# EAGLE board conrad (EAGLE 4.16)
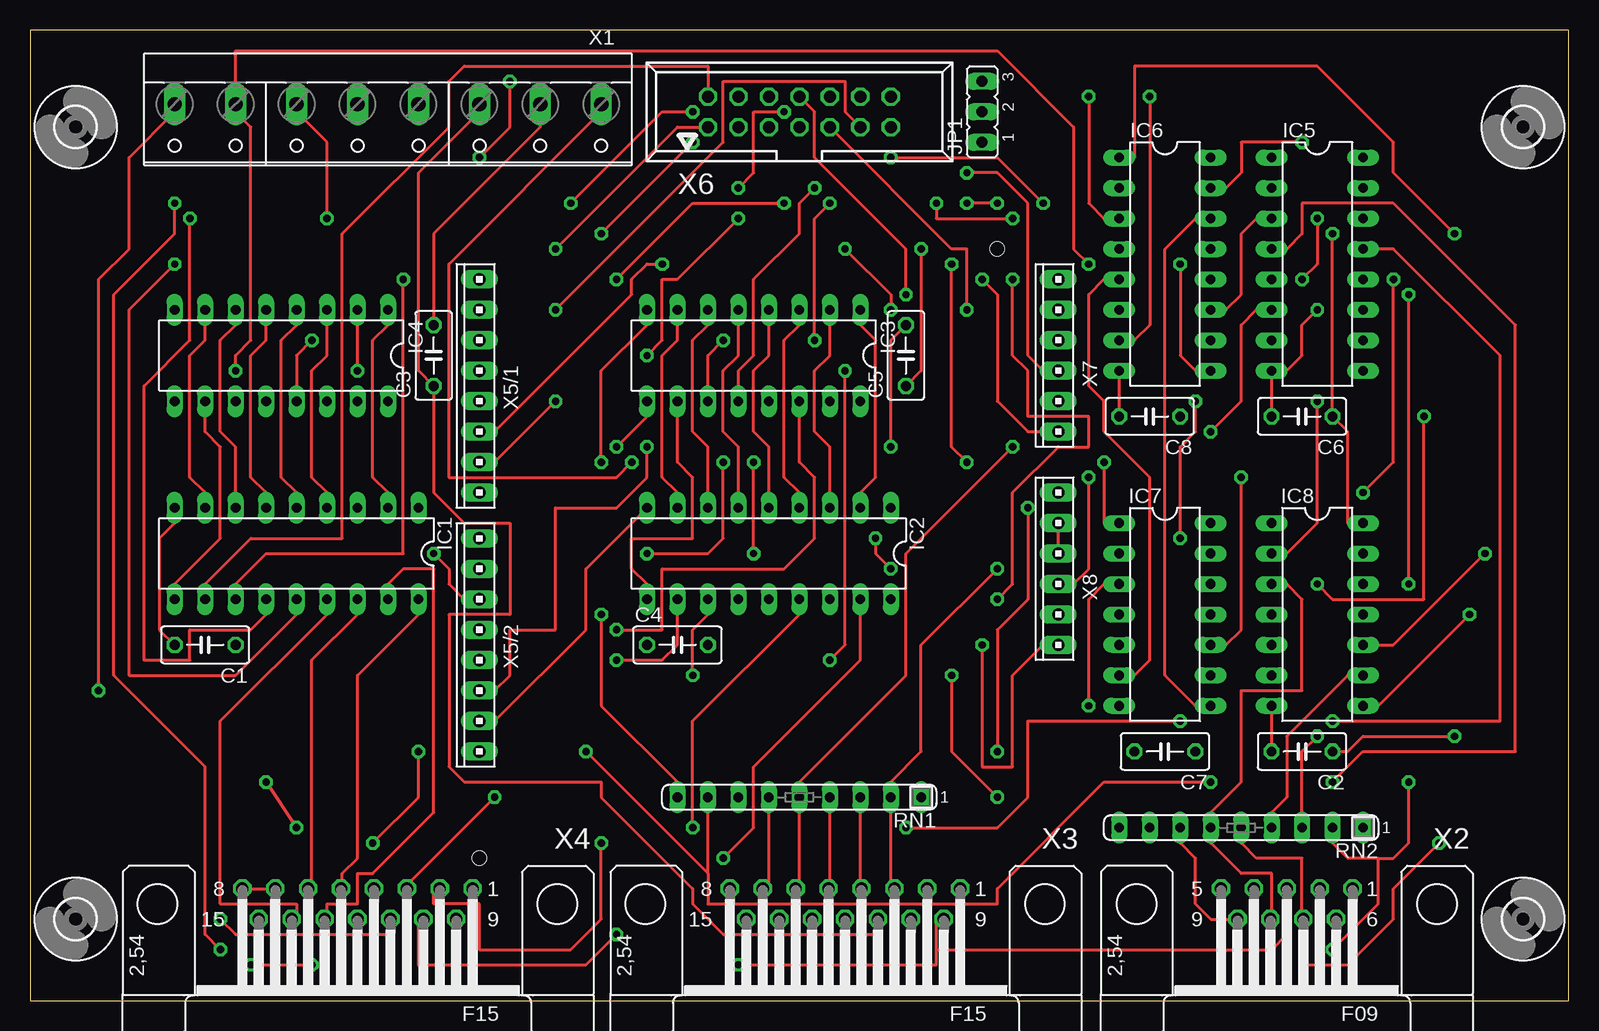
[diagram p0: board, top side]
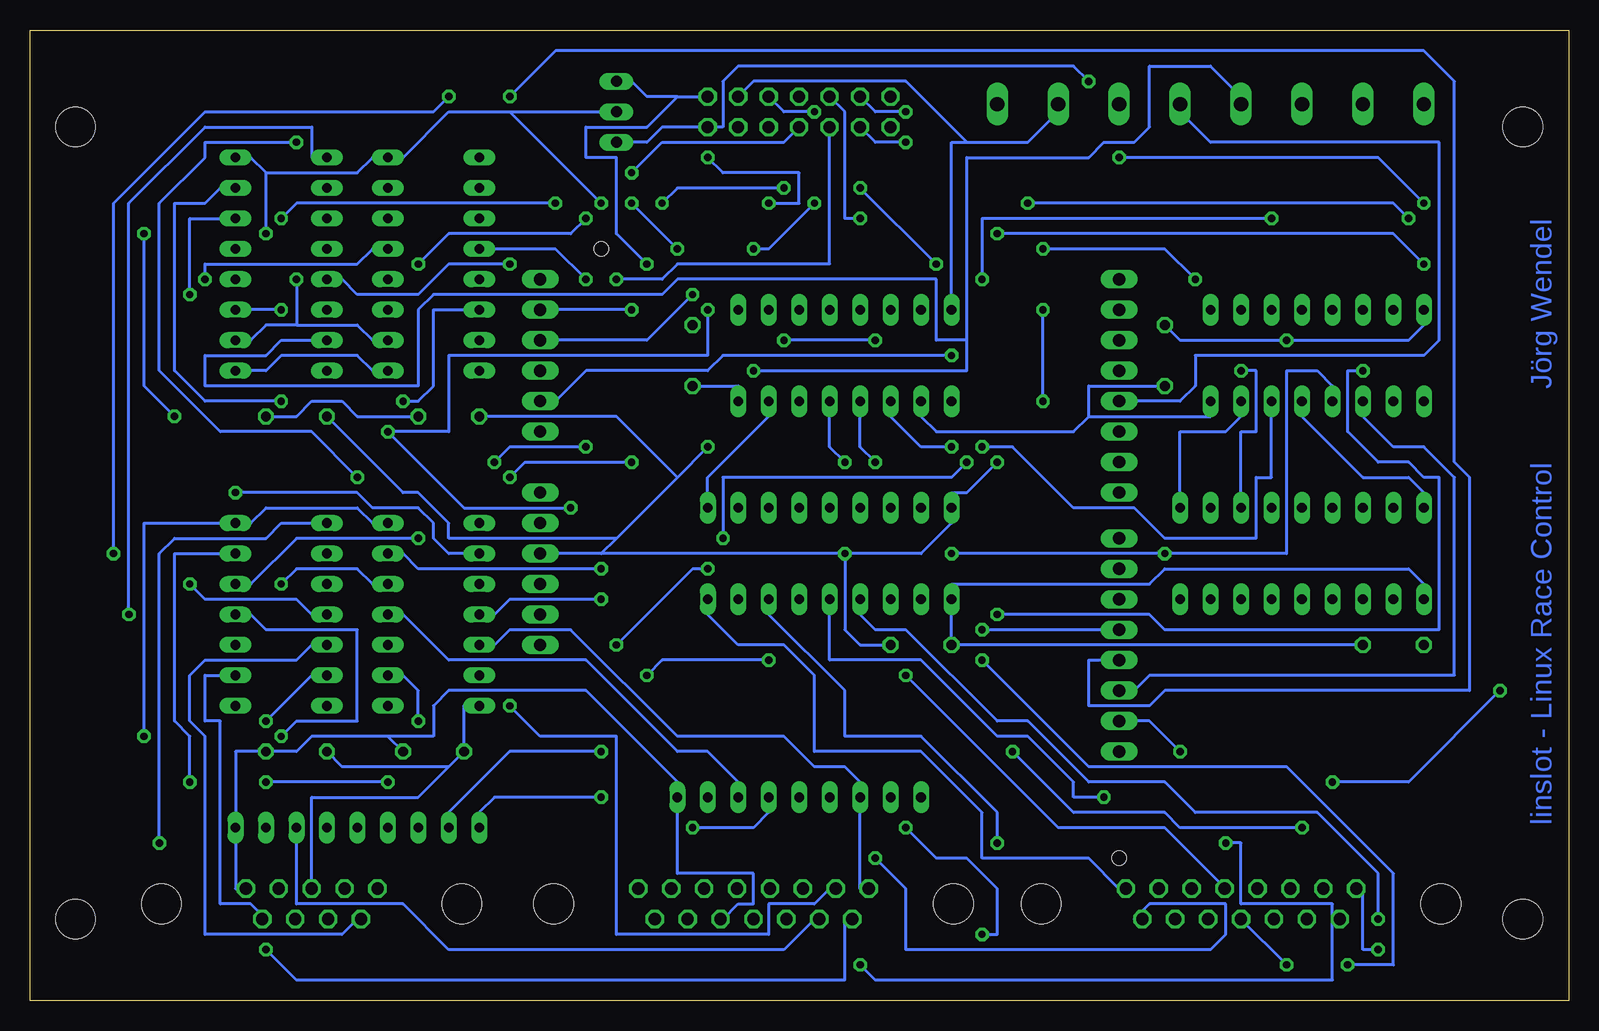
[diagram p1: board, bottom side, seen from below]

Size 128.25 x 80.95 mm. Coordinates in mm from the lower left corner, seen from the top.
Outline: 0,0 128.25,0 128.25,80.95 0,80.95 0,0
Copper layers (1*16): Top 0.035mm / dielectric 1.5mm / Bottom 0.035mm
Design rules "default": minimum track width 10mil, minimum drill 24mil, track to track 15mil, track to pad 15mil, pad to pad 15mil, via to via 15mil, smd to smd 8mil, copper to edge 40mil, drill to drill 15mil, minimum pad ring 10mil, minimum via ring 10mil, stop-mask expansion 4mil, vias tented up to drill 0mil, thermal gap 10mil
Holes 1.2 mm at 80.64,62.7 37.46,11.9

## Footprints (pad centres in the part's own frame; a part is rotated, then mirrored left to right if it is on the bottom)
3,3 = hole 3.3: 0,0
C050-030X075 = drill 0.813 octagon: 1 -2.54,0; 2 2.54,0
DIL18 = drill 0.813 long: 1 -10.16,-3.81; 2 -7.62,-3.81; 3 -5.08,-3.81; 4 -2.54,-3.81; 5 0,-3.81; 6 2.54,-3.81; 7 5.08,-3.81; 8 7.62,-3.81; 9 10.16,-3.81; 10 10.16,3.81; 11 7.62,3.81; 12 5.08,3.81; 13 2.54,3.81; 14 0,3.81; 15 -2.54,3.81; 16 -5.08,3.81; 17 -7.62,3.81; 18 -10.16,3.81
DIL16 = drill 0.813 long: 1 -8.89,-3.81; 2 -6.35,-3.81; 3 -3.81,-3.81; 4 -1.27,-3.81; 5 1.27,-3.81; 6 3.81,-3.81; 7 6.35,-3.81; 8 8.89,-3.81; 9 8.89,3.81; 10 6.35,3.81; 11 3.81,3.81; 12 1.27,3.81; 13 -1.27,3.81; 14 -3.81,3.81; 15 -6.35,3.81; 16 -8.89,3.81
DIL14 = drill 0.813 long: 1 -7.62,-3.81; 2 -5.08,-3.81; 3 -2.54,-3.81; 4 0,-3.81; 5 2.54,-3.81; 6 5.08,-3.81; 7 7.62,-3.81; 8 7.62,3.81; 9 5.08,3.81; 10 2.54,3.81; 11 0,3.81; 12 -2.54,3.81; 13 -5.08,3.81; 14 -7.62,3.81
JP2 = drill 0.914 long: 1 -2.54,0; 2 0,0; 3 2.54,0
SIL9 = drill 0.813 long: 1 -10.16,0; 2 -7.62,0; 3 -5.08,0; 4 -2.54,0; 5 0,0; 6 2.54,0; 7 5.08,0; 8 7.62,0; 9 10.16,0
W237-8P = drill 1.194 long: 1 -17.78,-0.635; 2 -12.7,-0.635; 3 -7.62,-0.635; 4 -2.54,-0.635; 5 2.54,-0.635; 6 7.62,-0.635; 7 12.7,-0.635; 8 17.78,-0.635
F09H = drill 1.016 octagon: 1 -5.486,-1.27; 2 -2.743,-1.27; 3 0,-1.27; 4 2.743,-1.27; 5 5.486,-1.27; 6 -4.115,1.27; 7 -1.372,1.27; 8 1.372,1.27; 9 4.115,1.27 | hole 3.302: -12.522,0; 12.522,0
F15H = drill 1.016 octagon: 1 -9.601,-1.27; 2 -6.858,-1.27; 3 -4.115,-1.27; 4 -1.372,-1.27; 5 1.372,-1.27; 6 4.115,-1.27; 7 6.858,-1.27; 8 9.601,-1.27; 9 -8.23,1.27; 10 -5.486,1.27; 11 -2.743,1.27; 12 0,1.27; 13 2.743,1.27; 14 5.486,1.27; 15 8.23,1.27 | hole 3.302: -16.662,0; 16.662,0
10X08MTA = drill 1.016 long: 1 8.89,0; 2 6.35,0; 3 3.81,0; 4 1.27,0; 5 -1.27,0; 6 -3.81,0; 7 -6.35,0; 8 -8.89,0
057-014-1 = drill 1 octagon: 1 -7.62,-1.27; 2 -7.62,1.27; 3 -5.08,-1.27; 4 -5.08,1.27; 5 -2.54,-1.27; 6 -2.54,1.27; 7 0,-1.27; 8 0,1.27; 9 2.54,-1.27; 10 2.54,1.27; 11 5.08,-1.27; 12 5.08,1.27; 13 7.62,-1.27; 14 7.62,1.27
10X06MTA = drill 1.016 long: 1 6.35,0; 2 3.81,0; 3 1.27,0; 4 -1.27,0; 5 -3.81,0; 6 -6.35,0

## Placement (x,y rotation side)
BOHRUNG0  [3,3]  3.8,6.82 0 top
BOHRUNG1  [3,3]  3.8,72.86 0 top
BOHRUNG2  [3,3]  124.46,72.86 0 top
BOHRUNG3  [3,3]  124.46,6.82 0 top
C1  0.1µ  [C050-030X075]  14.6,29.68 180 top
C2  0.1µ  [C050-030X075]  106.04,20.79 180 top
C3  0.1µ  [C050-030X075]  33.65,53.81 90 top
C4  0.1µ  [C050-030X075]  53.97,29.68 0 top
C5  0.1µ  [C050-030X075]  73.02,53.81 90 top
C6  0.1µ  [C050-030X075]  106.04,48.73 180 top
C7  0.1µ  [C050-030X075]  94.61,20.79 180 top
C8  0.1µ  [C050-030X075]  93.34,48.73 180 top
IC1  ULN 2803  [DIL18]  22.22,37.3 180 top
IC2  ULN 2803  [DIL18]  61.59,37.3 180 top
IC3  74HC595N  [DIL16]  60.32,53.81 180 top
IC4  74HC595N  [DIL16]  20.95,53.81 180 top
IC5  4021N  [DIL16]  107.31,61.43 270 top
IC6  4021N  [DIL16]  94.61,61.43 270 top
IC7  7414N  [DIL14]  94.61,32.22 270 top
IC8  7414N  [DIL14]  107.31,32.22 270 top
JP1  Jumper 3-pol  [JP2]  79.37,74.13 90 top
RN1  2k2  [SIL9]  64.13,16.98 180 top
RN2  2k2  [SIL9]  100.96,14.44 180 top
X1  Schraubkemme 8-pol  [W237-8P]  29.84,74.13 180 top
X2  DSUB 9-pol abgewinkelt  [F09H]  104.77,8.09 180 top
X3  DSUB 15-pol abgewinkelt  [F15H]  67.94,8.09 180 top
X4  DSUB 15-pol abgewinkelt  [F15H]  27.3,8.09 180 top
X5/1  Pfostenfeldstecker einreihig 8-pol  [10X08MTA]  37.46,51.27 90 top
X5/2  Pfostenfeldstecker einreihig 8-pol  [10X08MTA]  37.46,29.68 90 top
X6  Pfostenfeldstecker zweireihig 14-pol  [057-014-1]  64.13,74.13 0 top
X7  Pfostenfeldstecker einreihig 6-pol  [10X06MTA]  85.72,53.81 90 top
X8  Pfostenfeldstecker einreihig 6-pol  [10X06MTA]  85.72,36.03 90 top

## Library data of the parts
BOHRUNG0 BOHRUNG1-BOHRUNG3 = holes
C1-C8 = rcl
IC1 IC2 = uln-udn
IC3 IC4 IC7 IC8 = 74xx-eu
IC5 IC6 = 40xx
JP1 = jumper
RN1 RN2 = resistor-sil
X1 = con-wago-508
X2-X4 = con-subd
X5/1 X5/2 X7 X8 = con-amp
X6 = con-panduit

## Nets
+5V: C1.1 C2.1 C3.1 C4.1 C5.1 C6.1 C7.1 C8.1 IC1.10 IC2.10 IC3.10 IC3.16 IC4.10 IC4.16 IC5.16 IC6.16 IC7.14 IC8.14 JP1.2 RN1.1 RN2.1 X1.3 X2.1 X3.11
+5V/1: JP1.1 X4.7 X4.8 X6.13
+5V/2: JP1.3 X6.14 X8.4
GND: C1.2 C2.2 C3.2 C4.2 C5.2 C6.2 C7.2 C8.2 IC1.9 IC2.9 IC3.8 IC3.13 IC4.8 IC4.13 IC5.8 IC5.11 IC6.8 IC7.7 IC8.7 X1.2 X2.3 X3.9 X4.15 X5/2.7 X6.12 X8.2 X8.3
N$1: IC2.1 IC3.15
N$2: IC2.2 IC3.1
N$3: IC2.3 IC3.2
N$4: IC2.4 IC3.3
N$5: IC2.5 IC3.4
N$6: IC2.6 IC3.5
N$7: IC2.7 IC3.6
N$8: IC2.8 IC3.7
N$9: IC1.1 IC4.15
N$10: IC1.2 IC4.1
N$11: IC1.3 IC4.2
N$12: IC1.4 IC4.3
N$13: IC1.5 IC4.4
N$14: IC1.6 IC4.5
N$15: IC1.7 IC4.6
N$16: IC1.8 IC4.7
N$17: IC3.9 IC4.14
N$18: IC3.14 X5/2.4
N$19: IC3.11 IC4.11 IC5.10 IC6.10 X5/2.6
N$20: IC3.12 IC4.12 IC5.9 IC6.9 X5/2.3
N$21: IC2.12 X4.4
N$22: IC1.15 X4.14
N$23: IC1.16 X4.6
N$24: IC1.17 X4.13
N$25: IC1.18 X4.5
N$26: IC2.13 X4.11
N$27: IC2.14 X4.3
N$28: IC2.15 X4.10
N$29: IC2.16 X4.2
N$30: IC2.17 X4.9
N$31: IC2.18 X4.1
N$32: IC2.11 X4.12
N$33: IC6.3 X5/2.5
N$34: IC5.3 IC6.11
N$35: IC5.14 IC8.4
N$36: IC5.13 IC8.6
N$37: IC6.5 IC7.6
N$38: IC5.15 IC8.2
N$39: IC5.1 IC8.8
N$40: IC6.7 IC8.10
N$41: IC6.6 IC8.12
N$42: IC6.4 IC7.4
N$43: IC6.13 IC7.2
N$44: IC6.14 IC7.8
N$45: IC6.15 IC7.10
N$46: IC6.1 IC7.12
N$47: IC7.5 RN1.7 X3.8
N$48: IC7.3 RN1.6 X3.7
N$49: IC7.1 RN1.5 X3.6
N$50: IC7.9 RN1.4 X3.5
N$51: IC7.11 RN1.3 X3.4
N$52: IC7.13 RN1.2 X3.3
N$53: IC8.5 RN2.7 X2.9
N$54: IC8.3 RN2.6 X2.8
N$55: IC8.1 RN2.5 X2.7
N$56: IC8.9 RN2.4 X2.6
N$57: IC8.11 RN2.3 X3.14
N$58: IC8.13 RN2.2 X3.15
N$59: IC5.4 RN1.8 X1.8
N$60: IC5.5 RN1.9 X1.7
N$61: IC5.6 RN2.8 X1.6
N$62: IC5.7 RN2.9 X1.5
N$63: X1.4 X5/1.5
N$64: X6.7 X7.4
N$65: X6.8 X7.3
N$66: X6.9 X7.2
N$67: IC1.14 X6.3
N$68: IC1.13 X6.4
N$69: IC1.12 X6.1
N$70: IC1.11 X6.2
N$71: X6.5 X7.6
N$72: X6.6 X7.5
N$73: X5/1.6 X6.10
N$74: X1.1 X8.6
N$75: X5/1.7 X6.11

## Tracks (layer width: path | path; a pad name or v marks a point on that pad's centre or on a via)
+5V  (via drill 0.61)
  Top 0.254: X1.3 37.46,74.13 32.38,69.05 32.38,52.54 C3.1 33.65,42.38 36.19,39.84 40,39.84 40,32.22 34.92,32.22 34.92,19.52 36.19,18.25 47.62,18.25 47.62,16.98 55.24,9.36 55.24,8.09 57.78,5.55 70.48,5.55 70.48,6.82 X3.11 | IC1.10 12.06,34.76 15.87,38.57 15.87,46.19 14.6,47.46 IC4.10 | IC3.10 53.97,44.92 55.24,43.65 55.24,38.57 50.16,38.57 50.16,36.03 51.43,34.76 IC2.10 | IC8.14 109.85,39.84 109.85,47.46 C6.1 v108.58,63.97 | C5.1 74.29,52.54 v74.29,62.7 | v80.64,66.51 v78.1,66.51 | C2.1 109.85,20.79 111.12,22.06 v118.74,22.06
  Bottom 0.254: 40,48.73 29.84,48.73 IC4.16 | 40,48.73 40,51.27 C3.1 | 40,48.73 41.27,47.46 52.7,47.46 53.97,48.73 IC3.10 | C1.1 C4.1 IC2.10 51.43,34.76 34.92,34.76 33.65,36.03 13.33,36.03 12.06,34.76 IC1.10 | X3.11 70.48,6.82 69.21,8.09 67.94,8.09 67.94,10.63 74.29,10.63 RN1.1 74.29,18.25 81.91,25.87 93.34,25.87 94.61,24.6 94.61,22.06 98.42,22.06 | 109.85,9.36 X2.1 111.12,9.36 RN2.1 111.12,20.79 C2.1 106.04,20.79 104.77,22.06 98.42,22.06 | 98.42,22.06 C7.1 | C8.1 100.96,48.73 102.23,50 104.77,50 106.04,48.73 C6.1 | IC7.14 99.69,39.84 100.96,41.11 108.58,41.11 109.85,39.84 IC8.14 118.74,39.84 v118.74,22.06 | C5.1 69.21,51.27 IC3.16 | 88.26,74.13 93.34,74.13 97.15,70.32 IC6.16 99.69,70.32 100.96,69.05 108.58,69.05 | 88.26,74.13 JP1.2 | 108.58,69.05 109.85,70.32 IC5.16 | v78.1,66.51 v74.29,62.7 | 88.26,74.13 v80.64,66.51 | v108.58,63.97 108.58,69.05
+5V/1  (via drill 0.61)
  Top 0.254: X4.8 X4.7 20.95,9.36 | v15.87,4.28 14.6,5.55 14.6,19.52 6.98,27.14 6.98,58.89 12.06,63.97 v12.06,66.51 | v37.46,70.32 40,72.86 v40,76.67
  Bottom 0.254: JP1.1 76.83,71.59 75.56,72.86 X6.13 70.48,72.86 70.48,76.67 69.21,77.94 41.27,77.94 v40,76.67 | v15.87,4.28 17.14,4.28 17.14,9.36 X4.8 | v12.06,66.51 15.87,70.32 v37.46,70.32
+5V/2  (via drill 0.61)
  Top 0.254: v88.26,43.65 88.26,36.03 86.99,34.76 X8.4 | v78.1,44.92 76.83,46.19 v76.83,61.43
  Bottom 0.254: 74.29,75.4 X6.14 | 74.29,75.4 76.83,75.4 78.1,76.67 JP1.3 | v88.26,43.65 86.99,44.92 v78.1,44.92 | v76.83,61.43 79.37,63.97 79.37,70.32 81.91,70.32 81.91,72.86 76.83,72.86 74.29,75.4
GND  (via drill 0.61)
  Top 0.254: C2.2 IC8.7 | v59.05,3.01 75.56,3.01 75.56,4.28 | 75.56,4.28 75.56,6.82 X3.9 | X2.3 104.77,5.55 103.5,4.28 75.56,4.28 | C1.2 10.79,30.95 10.79,38.57 12.06,39.84 IC1.9 | C3.2 33.65,63.97 42.54,72.86 X1.2 | v23.49,55.08 22.22,53.81 IC4.13 | C6.2 IC5.8 104.77,52.54 106.04,53.81 106.04,56.35 v107.31,57.62 | C8.2 IC6.8 | v60.32,37.3 v60.32,44.92 | C5.2 71.75,55.08 v71.75,46.19 | IC2.9 46.35,36.03 46.35,30.95 38.73,23.33 X5/2.7 | X8.3 X8.2 | v47.62,44.92 47.62,52.54 51.43,56.35 IC3.8 | v28.57,13.17 32.38,16.98 v32.38,20.79
  Bottom 0.254: IC7.7 92.07,24.6 C7.2 93.34,19.52 | X2.3 104.77,16.98 95.88,16.98 93.34,19.52 | C2.2 102.23,19.52 93.34,19.52 | 19.68,6.82 19.68,1.74 57.78,1.74 v59.05,3.01 | IC4.13 22.22,48.73 17.14,43.65 13.33,43.65 12.06,42.38 IC1.9 | C3.2 32.38,55.08 v23.49,55.08 13.33,55.08 12.06,56.35 IC4.8 | 50.16,71.59 45.08,71.59 42.54,74.13 X1.2 | 50.16,71.59 51.43,71.59 IC3.8 | X6.12 67.94,76.67 55.24,76.67 50.16,71.59 | v107.31,57.62 IC5.11 | v60.32,37.3 80.64,37.3 | v60.32,37.3 53.97,37.3 51.43,39.84 IC2.9 51.43,42.38 50.16,42.38 v47.62,44.92 | 80.64,37.3 X8.3 | C4.2 59.05,29.68 60.32,30.95 v60.32,37.3 | v60.32,44.92 61.59,46.19 IC3.13 | 80.64,37.3 79.37,38.57 | 79.37,38.57 74.29,43.65 | 74.29,43.65 v71.75,46.19 | C8.2 79.37,48.73 74.29,43.65 | C6.2 97.15,42.38 95.88,42.38 93.34,39.84 93.34,38.57 79.37,38.57 | 19.68,6.82 19.68,8.09 27.3,8.09 27.3,13.17 v28.57,13.17 | v32.38,20.79 34.92,23.33 X5/2.7 | 19.68,6.82 X4.15
N$1
  Bottom 0.254: IC3.15 66.67,48.73 71.75,43.65 IC2.1
N$2
  Top 0.254: IC2.2 69.21,42.38 70.48,43.65 70.48,55.08 69.21,56.35 IC3.1
N$3
  Top 0.254: IC2.3 66.67,46.19 65.4,47.46 65.4,52.54 66.67,53.81 IC3.2
N$4
  Top 0.254: IC2.4 64.13,42.38 62.86,43.65 62.86,55.08 64.13,56.35 IC3.3
N$5
  Top 0.254: IC2.5 61.59,46.19 60.32,47.46 60.32,52.54 61.59,53.81 IC3.4
N$6
  Top 0.254: IC2.6 59.05,46.19 57.78,47.46 57.78,52.54 59.05,53.81 IC3.5
N$7
  Top 0.254: IC2.7 56.51,46.19 55.24,47.46 55.24,55.08 56.51,56.35 IC3.6
N$8
  Top 0.254: IC2.8 53.97,42.38 52.7,43.65 52.7,53.81 53.97,55.08 IC3.7
N$9
  Bottom 0.254: IC1.1 32.38,47.46 28.57,47.46 27.3,48.73 IC4.15
N$10
  Top 0.254: IC1.2 29.84,42.38 28.57,43.65 28.57,55.08 29.84,56.35 IC4.1
N$11  (via drill 0.61)
  Top 0.254: v27.3,52.54 IC4.2
  Bottom 0.254: v27.3,52.54 26.03,52.54 26.03,47.46 27.3,47.46 IC1.3
N$12
  Top 0.254: IC1.4 24.76,42.38 23.49,43.65 23.49,52.54 24.76,53.81 IC4.3
N$13
  Top 0.254: IC1.5 22.22,42.38 20.95,43.65 20.95,55.08 22.22,56.35 IC4.4
N$14
  Top 0.254: IC1.6 19.68,42.38 18.41,43.65 18.41,53.81 19.68,55.08 IC4.5
N$15
  Top 0.254: IC1.7 17.14,46.19 15.87,47.46 15.87,55.08 17.14,56.35 IC4.6
N$16
  Top 0.254: IC1.8 14.6,42.38 13.33,43.65 13.33,53.81 14.6,55.08 IC4.7
N$17  (via drill 0.61)
  Top 0.254: v48.89,46.19 51.43,48.73 IC3.9
  Bottom 0.254: v48.89,46.19 46.35,46.19 41.27,41.11 36.19,41.11 33.65,38.57 26.03,38.57 26.03,43.65 24.76,43.65 IC4.14
N$18  (via drill 0.61)
  Top 0.254: v48.89,30.95 52.7,30.95 52.7,36.03 62.86,36.03 65.4,38.57 65.4,43.65 64.13,44.92 IC3.14
  Bottom 0.254: X5/2.4 v48.89,30.95
N$19  (via drill 0.61)
  Top 0.254: v51.43,46.19 51.43,43.65 48.89,41.11 43.81,41.11 43.81,30.95 40,30.95 40,27.14 38.73,25.87 X5/2.6 | v106.04,60.16 107.31,61.43 v107.31,65.24 | v84.45,66.51 80.64,70.32 v71.75,70.32 | v66.67,66.51 65.4,65.24 v65.4,55.08 | v57.78,55.08 56.51,53.81 IC3.11
  Bottom 0.254: 106.04,56.35 108.58,56.35 109.85,55.08 IC5.10 | 106.04,56.35 100.96,56.35 99.69,55.08 IC6.10 | IC4.11 17.14,48.73 14.6,46.19 12.06,46.19 9.52,43.65 9.52,27.14 34.92,27.14 36.19,25.87 X5/2.6 | v51.43,46.19 53.97,46.19 56.51,48.73 IC3.11 | v106.04,60.16 106.04,56.35 | v107.31,65.24 106.04,66.51 v84.45,66.51 | v71.75,70.32 70.48,69.05 64.13,69.05 64.13,66.51 v66.67,66.51 | v57.78,55.08 v65.4,55.08
N$20  (via drill 0.61)
  Top 0.254: v33.65,37.3 34.92,36.03 34.92,34.76 36.19,33.49 X5/2.3 | v57.78,44.92 57.78,38.57 56.51,37.3 v51.43,37.3 | v95.88,61.43 95.88,53.81 97.15,52.54 IC6.9 | v81.91,65.24 75.56,65.24 v75.56,66.51 | v65.4,67.78 64.13,66.51 64.13,63.97 60.32,60.16 60.32,53.81 59.05,52.54 IC3.12
  Bottom 0.254: IC6.9 99.69,52.54 100.96,53.81 107.31,53.81 108.58,52.54 IC5.9 | IC4.12 19.68,51.27 20.95,52.54 23.49,52.54 23.49,37.3 v33.65,37.3 v51.43,37.3 | v57.78,44.92 59.05,46.19 IC3.12 | v95.88,61.43 93.34,63.97 83.18,63.97 v81.91,65.24 | v75.56,66.51 74.29,67.78 v65.4,67.78
N$21  (via drill 0.61)
  Top 0.254: v55.24,27.14 55.24,30.95 56.51,32.22 IC2.12
  Bottom 0.254: v55.24,27.14 42.54,14.44 33.65,14.44 28.57,9.36 X4.4
N$22
  Top 0.254: IC1.15 24.76,32.22 15.87,23.33 15.87,8.09 22.22,8.09 22.22,6.82 X4.14
N$23
  Top 0.254: IC1.16 27.3,32.22 23.49,28.41 23.49,9.36 X4.6
N$24
  Top 0.254: IC1.17 29.84,34.76 31.11,36.03 33.65,36.03 33.65,15.71 28.57,10.63 27.3,10.63 27.3,8.09 24.76,8.09 24.76,6.82 X4.13
N$25
  Top 0.254: IC1.18 32.38,32.22 27.3,27.14 27.3,11.9 26.03,10.63 26.03,9.36 X4.5
N$26  (via drill 0.61)
  Top 0.254: v15.87,6.82 17.14,5.55 29.84,5.55 29.84,6.82 X4.11
  Bottom 0.254: v15.87,6.82 15.87,10.63 20.95,15.71 31.11,15.71 33.65,18.25 40,18.25 45.08,23.33 47.62,23.33 55.24,30.95 57.78,30.95 59.05,32.22 IC2.13
N$27  (via drill 0.61)
  Top 0.254: v38.73,16.98 31.11,9.36 X4.3
  Bottom 0.254: v38.73,16.98 41.27,16.98 41.27,18.25 45.08,22.06 47.62,22.06 53.97,28.41 61.59,28.41 IC2.14
N$28  (via drill 0.61)
  Top 0.254: v55.24,14.44 55.24,23.33 64.13,32.22 IC2.15 | v48.89,5.55 46.35,3.01 32.38,3.01 32.38,6.82 X4.10
  Bottom 0.254: v55.24,14.44 52.7,11.9 50.16,11.9 47.62,9.36 47.62,5.55 v48.89,5.55
N$29  (via drill 0.61)
  Top 0.254: v47.62,13.17 47.62,6.82 45.08,4.28 37.46,4.28 37.46,8.09 33.65,8.09 33.65,9.36 X4.2
  Bottom 0.254: v47.62,13.17 47.62,15.71 53.97,22.06 60.32,22.06 60.32,25.87 66.67,32.22 IC2.16
N$30  (via drill 0.61)
  Top 0.254: v57.78,11.9 60.32,14.44 60.32,19.52 69.21,28.41 IC2.17
  Bottom 0.254: v57.78,11.9 55.24,9.36 55.24,4.28 29.84,4.28 28.57,5.55 28.57,8.09 34.92,8.09 36.19,6.82 X4.9
N$31
  Bottom 0.254: IC2.18 71.75,32.22 69.21,29.68 65.4,29.68 62.86,27.14 62.86,20.79 53.97,20.79 48.89,15.71 48.89,11.9 40,11.9 37.46,9.36 X4.1
N$32  (via drill 0.61)
  Top 0.254: v48.89,28.41 52.7,28.41 53.97,29.68 IC2.11 | v18.41,3.01 v23.49,3.01
  Bottom 0.254: v48.89,28.41 40,19.52 23.49,19.52 14.6,10.63 14.6,3.01 v18.41,3.01 | v23.49,3.01 X4.12
N$33  (via drill 0.61)
  Top 0.254: v88.26,75.4 88.26,66.51 89.53,65.24 IC6.3
  Bottom 0.254: v88.26,75.4 84.45,79.21 12.06,79.21 9.52,76.67 9.52,44.92 8.25,43.65 8.25,25.87 33.65,25.87 34.92,24.6 40,24.6 40,28.41 X5/2.5
N$34
  Top 0.254: IC6.11 99.69,57.62 100.96,58.89 100.96,63.97 102.23,65.24 IC5.3
N$35  (via drill 0.61)
  Top 0.254: v114.93,34.76 v114.93,58.89
  Bottom 0.254: v114.93,34.76 113.66,33.49 106.04,33.49 104.77,32.22 IC8.4 | v114.93,58.89 114.93,65.24 IC5.14
N$36  (via drill 0.61)
  Top 0.254: v108.58,23.33 122.55,23.33 122.55,53.81 113.66,62.7 IC5.13
  Bottom 0.254: v108.58,23.33 104.77,27.14 IC8.6
N$37
  Top 0.254: IC7.6 92.07,27.14 93.34,28.41 93.34,43.65 89.53,47.46 89.53,50 88.26,51.27 88.26,58.89 89.53,60.16 IC6.5
N$38  (via drill 0.61)
  Top 0.254: v107.31,50 107.31,39.84 104.77,37.3 IC8.2
  Bottom 0.254: v107.31,50 113.66,50 116.2,52.54 116.2,66.51 113.66,66.51 112.39,67.78 IC5.15
N$39  (via drill 0.61)
  Top 0.254: v120.01,32.22 112.39,24.6 IC8.8
  Bottom 0.254: v120.01,32.22 120.01,66.51 113.66,72.86 104.77,72.86 104.77,70.32 IC5.1
N$40  (via drill 0.61)
  Top 0.254: v93.34,75.4 93.34,56.35 92.07,55.08 IC6.7 | v121.28,37.3 113.66,29.68 IC8.10
  Bottom 0.254: v93.34,75.4 94.61,74.13 113.66,74.13 121.28,66.51 v121.28,37.3
N$41  (via drill 0.61)
  Top 0.254: v95.88,38.57 95.88,46.19 97.15,47.46 v97.15,50
  Bottom 0.254: v95.88,38.57 106.04,38.57 109.85,34.76 IC8.12 | v97.15,50 95.88,50 94.61,51.27 94.61,57.62 IC6.6
N$42  (via drill 0.61)
  Top 0.254: v80.64,33.49 81.91,34.76 81.91,42.38 85.72,46.19 88.26,46.19 88.26,48.73 83.18,48.73 83.18,52.54 81.91,53.81 v81.91,60.16
  Bottom 0.254: v80.64,33.49 88.26,33.49 89.53,32.22 IC7.4 | v81.91,60.16 84.45,62.7 IC6.4
N$43  (via drill 0.61)
  Top 0.254: v111.12,42.38 113.66,44.92 v113.66,60.16
  Bottom 0.254: v111.12,42.38 100.96,42.38 99.69,41.11 95.88,41.11 94.61,39.84 94.61,38.57 93.34,37.3 IC7.2 | v113.66,60.16 113.66,61.43 100.96,61.43 99.69,62.7 IC6.13
N$44
  Top 0.254: IC7.8 97.15,24.6 94.61,27.14 94.61,62.7 97.15,65.24 IC6.14
N$45  (via drill 0.61)
  Top 0.254: v100.96,43.65 100.96,30.95 99.69,29.68 IC7.10 | v106.04,71.59 100.96,71.59 100.96,69.05 99.69,67.78 IC6.15
  Bottom 0.254: v100.96,43.65 104.77,47.46 112.39,47.46 117.47,52.54 117.47,66.51 113.66,70.32 113.66,71.59 v106.04,71.59
N$46  (via drill 0.61)
  Top 0.254: v107.31,34.76 108.58,33.49 116.2,33.49 v116.2,48.73 | v118.74,63.97 113.66,69.05 113.66,71.59 107.31,77.94 92.07,77.94 92.07,70.32 IC6.1
  Bottom 0.254: v107.31,34.76 106.04,36.03 100.96,36.03 99.69,34.76 IC7.12 | v116.2,48.73 118.74,51.27 v118.74,63.97
N$47
  Bottom 0.254: X3.8 59.05,9.36 RN1.7 59.05,18.25 60.32,19.52 62.86,19.52 65.4,22.06 74.29,22.06 83.18,30.95 88.26,30.95 89.53,29.68 IC7.5
N$48  (via drill 0.61)
  Top 0.254: RN1.6 61.59,9.36 X3.7 | v88.26,24.6 88.26,33.49 89.53,34.76 IC7.3
  Bottom 0.254: v88.26,24.6 85.72,22.06 79.37,22.06 79.37,5.55 66.67,5.55 66.67,8.09 62.86,8.09 61.59,9.36 X3.7
N$49  (via drill 0.61)
  Top 0.254: X3.6 64.13,9.36 RN1.5 64.13,18.25 73.02,27.14 73.02,37.3 v81.91,46.19 | v89.53,44.92 89.53,39.84 IC7.1
  Bottom 0.254: v89.53,44.92 88.26,46.19 v81.91,46.19
N$50  (via drill 0.61)
  Top 0.254: RN1.4 66.67,9.36 X3.5 | v95.88,23.33 83.18,23.33 83.18,16.98 80.64,14.44 v73.02,14.44
  Bottom 0.254: v95.88,23.33 95.88,25.87 97.15,27.14 IC7.9 | v73.02,14.44 67.94,14.44 66.67,15.71 RN1.4
N$51
  Top 0.254: RN1.3 69.21,9.36 X3.4
  Bottom 0.254: IC7.11 97.15,32.22 93.34,28.41 81.91,28.41 74.29,20.79 71.75,20.79 69.21,18.25 RN1.3
N$52  (via drill 0.61)
  Top 0.254: X3.3 71.75,9.36 RN1.2 71.75,18.25 74.29,20.79 74.29,29.68 v80.64,36.03
  Bottom 0.254: v80.64,36.03 95.88,36.03 97.15,37.3 IC7.13
N$53
  Top 0.254: RN2.7 95.88,13.17 97.15,11.9 97.15,8.09 98.42,6.82 X2.9 100.96,6.82
  Bottom 0.254: IC8.5 104.77,29.68 106.04,28.41 113.66,28.41 114.93,27.14 114.93,23.33 113.66,22.06 113.66,5.55 102.23,5.55 100.96,6.82 X2.9
N$54
  Top 0.254: X2.8 103.5,6.82 103.5,10.63 100.96,10.63 98.42,13.17 RN2.6 98.42,15.71 100.96,18.25 100.96,25.87 106.04,25.87 106.04,33.49 104.77,34.76 IC8.3
N$55  (via drill 0.61)
  Top 0.254: 106.04,6.82 106.04,11.9 102.23,11.9 100.96,13.17 RN2.5 | v117.47,13.17 113.66,9.36 113.66,6.82 109.85,3.01 106.04,3.01 106.04,6.82 | 106.04,6.82 X2.7
  Bottom 0.254: v117.47,13.17 117.47,37.3 116.2,38.57 108.58,38.57 107.31,39.84 IC8.1
N$56
  Top 0.254: RN2.4 103.5,15.71 104.77,16.98 104.77,22.06 109.85,27.14 IC8.9
  Bottom 0.254: X2.6 108.58,6.82 109.85,8.09 112.39,8.09 112.39,23.33 113.66,23.33 113.66,27.14 IC8.9
N$57  (via drill 0.61)
  Top 0.254: v107.31,22.06 106.04,20.79 RN2.3
  Bottom 0.254: RN2.3 106.04,8.09 97.15,8.09 93.34,4.28 65.4,4.28 62.86,6.82 X3.14 | v107.31,22.06 106.04,23.33 100.96,23.33 100.96,30.95 108.58,30.95 109.85,32.22 IC8.11
N$58  (via drill 0.61)
  Top 0.254: 112.39,11.9 113.66,11.9 114.93,13.17 v114.93,18.25 | 112.39,11.9 109.85,11.9 108.58,13.17 RN2.2 | v108.58,4.28 112.39,8.09 112.39,11.9
  Bottom 0.254: v114.93,18.25 114.93,22.06 116.2,23.33 116.2,37.3 IC8.13 | v108.58,4.28 106.04,1.74 60.32,1.74 60.32,6.82 X3.15
N$59  (via drill 0.61)
  Top 0.254: 56.51,10.63 56.51,8.09 80.64,8.09 80.64,9.36 89.53,18.25 v98.42,18.25 | v108.58,18.25 111.12,20.79 123.82,20.79 123.82,56.35 113.66,66.51 106.04,66.51 106.04,63.97 104.77,62.7 IC5.4 | 56.51,10.63 RN1.8 | v5.71,25.87 5.71,60.16 8.25,62.7 8.25,70.32 12.06,74.13 X1.8 | v19.68,18.25 v22.22,14.44 | v46.35,20.79 56.51,10.63
  Bottom 0.254: v98.42,18.25 v108.58,18.25 | v5.71,25.87 13.33,18.25 v19.68,18.25 | v22.22,14.44 32.38,14.44 33.65,15.71 41.27,15.71 v46.35,20.79
N$60  (via drill 0.61)
  Top 0.254: v47.62,32.22 47.62,24.6 53.97,18.25 RN1.9 | v17.14,52.54 17.14,53.81 18.41,55.08 18.41,72.86 17.14,74.13 X1.7 17.14,79.21 80.64,79.21 86.99,72.86 86.99,62.7 v88.26,61.43
  Bottom 0.254: v47.62,32.22 34.92,32.22 33.65,30.95 10.79,30.95 10.79,43.65 12.06,43.65 13.33,44.92 15.87,44.92 18.41,47.46 18.41,52.54 v17.14,52.54 | v88.26,61.43 93.34,61.43 95.88,58.89 100.96,58.89 102.23,60.16 IC5.5
N$61  (via drill 0.61)
  Top 0.254: v80.64,20.79 80.64,30.95 83.18,33.49 v83.18,41.11 | v98.42,47.46 100.96,50 100.96,56.35 102.23,57.62 IC5.6 | v24.76,65.24 24.76,71.59 22.22,74.13 X1.6 | v48.89,60.16 55.24,66.51 v62.86,66.51 | v67.94,62.7 71.75,58.89 v71.75,57.62
  Bottom 0.254: v80.64,20.79 88.26,20.79 93.34,15.71 RN2.8 | v83.18,41.11 92.07,41.11 v98.42,47.46 93.34,47.46 93.34,53.81 71.75,53.81 v71.75,57.62 | v24.76,65.24 48.89,65.24 v48.89,60.16 | v62.86,66.51 66.67,62.7 v67.94,62.7
N$62  (via drill 0.61)
  Top 0.254: v80.64,16.98 76.83,20.79 v76.83,27.14 | v66.67,28.41 67.94,29.68 v67.94,52.54
  Bottom 0.254: v80.64,16.98 89.53,16.98 90.8,15.71 RN2.9 | v76.83,27.14 75.56,28.41 v66.67,28.41 | v67.94,52.54 50.16,52.54 50.16,55.08 | 50.16,55.08 50.16,70.32 40,70.32 38.73,71.59 36.19,71.59 34.92,72.86 34.92,77.94 29.84,77.94 27.3,75.4 X1.5 | 50.16,55.08 52.7,55.08 52.7,60.16 74.29,60.16 75.56,58.89 94.61,58.89 95.88,57.62 95.88,51.27 113.66,51.27 113.66,53.81 108.58,53.81 107.31,55.08 IC5.7
N$63
  Bottom 0.254: X5/1.5 32.38,50 31.11,51.27 31.11,53.81 12.06,53.81 10.79,55.08 10.79,71.59 29.84,71.59 32.38,74.13 X1.4
N$64  (via drill 0.61)
  Top 0.254: v78.1,69.05 80.64,69.05 83.18,66.51 83.18,53.81 84.45,52.54 X7.4
  Bottom 0.254: X6.7 65.4,71.59 75.56,71.59 v78.1,69.05
N$65  (via drill 0.61)
  Top 0.254: X6.8 65.4,74.13 65.4,70.32 73.02,62.7 v73.02,58.89
  Bottom 0.254: v73.02,58.89 76.83,55.08 X7.3
N$66  (via drill 0.61)
  Top 0.254: X6.9 76.83,62.7 78.1,62.7 v78.1,57.62
  Bottom 0.254: v78.1,57.62 X7.2
N$67  (via drill 0.61)
  Top 0.254: v12.06,61.43 8.25,57.62 8.25,27.14 17.14,27.14 22.22,32.22 IC1.14 | v47.62,63.97 v55.24,71.59
  Bottom 0.254: v12.06,61.43 14.6,63.97 v47.62,63.97 | v55.24,71.59 57.78,71.59 X6.3
N$68  (via drill 0.61)
  Top 0.254: v13.33,65.24 13.33,55.08 9.52,51.27 9.52,28.41 13.33,28.41 13.33,30.95 18.41,30.95 19.68,32.22 IC1.13 | v45.08,66.51 52.7,74.13 v55.24,74.13
  Bottom 0.254: v13.33,65.24 14.6,66.51 v45.08,66.51 | v55.24,74.13 57.78,74.13 X6.4
N$69  (via drill 0.61)
  Top 0.254: v31.11,60.16 31.11,37.3 19.68,37.3 17.14,34.76 IC1.12 | v43.81,62.7 53.97,72.86 X6.1
  Bottom 0.254: v31.11,60.16 33.65,62.7 v43.81,62.7
N$70
  Top 0.254: X6.2 56.51,77.94 36.19,77.94 34.92,76.67 34.92,72.86 26.03,63.97 26.03,38.57 18.41,38.57 14.6,34.76 IC1.11
N$71  (via drill 0.61)
  Top 0.254: v79.37,60.16 80.64,58.89 80.64,50 83.18,47.46 X7.6
  Bottom 0.254: X6.5 61.59,61.43 74.29,61.43 75.56,60.16 v79.37,60.16
N$72  (via drill 0.61)
  Top 0.254: v59.05,65.24 53.97,60.16 52.7,60.16 52.7,55.08 v51.43,53.81
  Bottom 0.254: X6.6 60.32,74.13 60.32,65.24 v59.05,65.24 | v51.43,53.81 70.48,53.81 71.75,52.54 81.91,52.54 84.45,50 X7.5
N$73  (via drill 0.61)
  Top 0.254: v62.86,74.13 60.32,74.13 60.32,69.05 v59.05,67.78 | v52.7,61.43 51.43,61.43 50.16,60.16 50.16,58.89 38.73,47.46 X5/1.6
  Bottom 0.254: X6.10 65.4,74.13 v62.86,74.13 | v52.7,61.43 v59.05,67.78
N$74  (via drill 0.61)
  Top 0.254: v79.37,29.68 79.37,19.52 81.91,19.52 81.91,27.14 84.45,29.68 X8.6 | v71.75,36.03 70.48,37.3 v70.48,38.57 | v50.16,44.92 48.89,43.65 34.92,43.65 34.92,61.43 47.62,74.13 X1.1
  Bottom 0.254: v79.37,29.68 73.02,36.03 v71.75,36.03 | v70.48,38.57 70.48,43.65 51.43,43.65 v50.16,44.92
N$75  (via drill 0.61)
  Top 0.254: X6.11 67.94,74.13 67.94,76.67 57.78,76.67 57.78,71.59 v43.81,57.62 | v43.81,50 38.73,44.92 X5/1.7
  Bottom 0.254: v43.81,50 v43.81,57.62

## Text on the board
Bottom: Jörg Wendel | linslot - Linux Race Control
